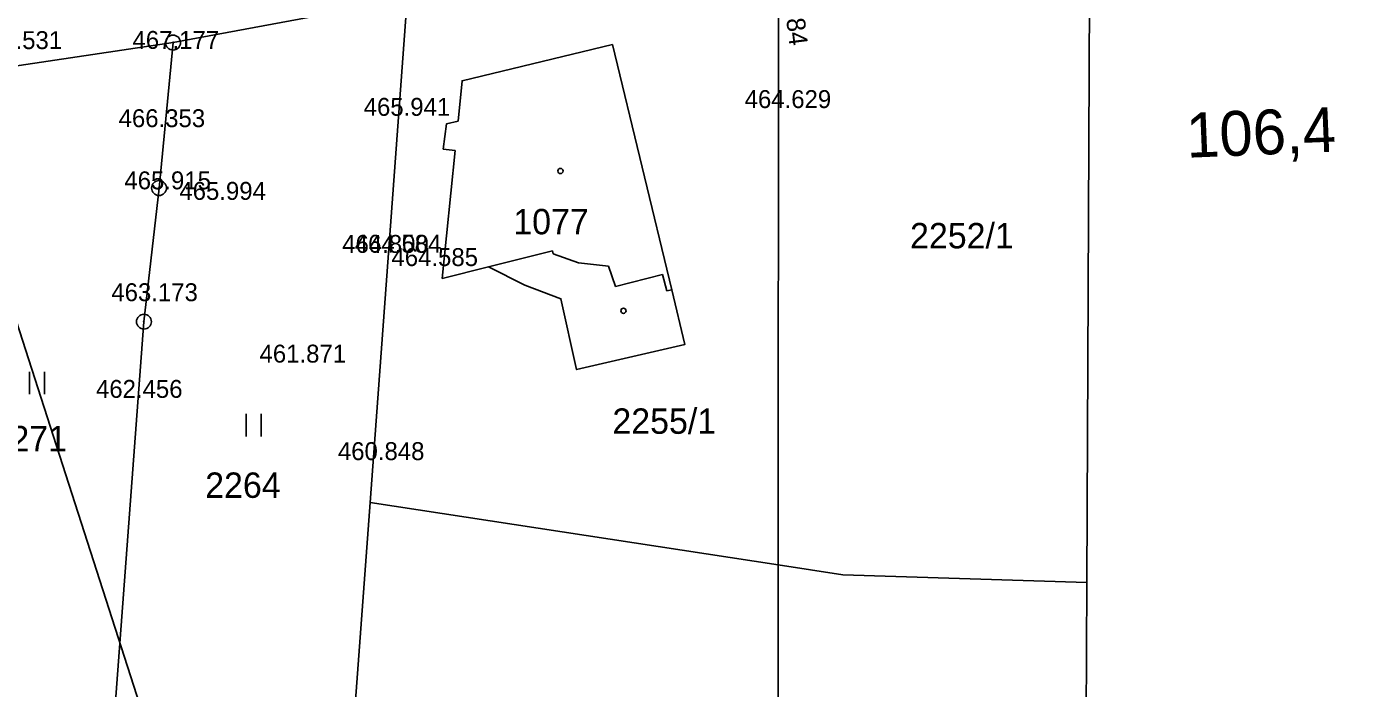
# Model space of a CAD drawing. Extents: x -758836 to -757729, y -1175316 to -1174366.
# Drawn here: x -758289.2 to -758200.5, y -1174833.7 to -1174789.4 of the extents above; entities that cross this region are included whole.
import ezdxf

# ---------------------------------------------------------------- set-up
doc = ezdxf.new("R2010")
doc.units = 0
for name, color, linetype in [('_NOR-návrh tenká', 7, 'Continuous'), ('_NOR-osa', 7, 'Continuous'), ('_NOR-pomocná', 7, 'Continuous'), ('_NOR-popis', 7, 'Continuous'), ('Hranice parcel', 7, 'Continuous'), ('Parcelní čísla', 7, 'Continuous'), ('Vnitřní kresba', 7, 'Continuous'), ('Vrstva 61', 7, 'Continuous'), ('Značky bodu BP', 7, 'Continuous'), ('Značky budov', 7, 'Continuous'), ('Značky kultur', 7, 'Continuous')]:
    doc.layers.add(name, color=color, linetype=linetype)

msp = doc.modelspace()

# ---------------------------------------------------------------- linework, layer by layer
at = {"layer": '_NOR-návrh tenká'}
for radius, start, end in [(295.6, 97.09776, 129.28488), (294.75, 97.0979, 129.28474), (293.75, 97.09807, 120.96729), (292.25, 97.09832, 120.96729), (291.3, 97.09848, 129.28417), (290.55, 97.09861, 129.28404)]:
    msp.add_arc((-758205.34, -1175057.864), radius, start, end, dxfattribs=at)
at = {"layer": '_NOR-osa'}
msp.add_arc((-758205.34, -1175057.864), 293, 97.09819, 129.28445, dxfattribs=at)
at = {"layer": '_NOR-pomocná'}
for points in [[(-758317.652, -1174723.031), (-758217.708, -1174690.839), (-758172.179, -1174832.187), (-758272.123, -1174864.38)], [(-758417.595, -1174755.224), (-758317.652, -1174723.031), (-758272.123, -1174864.38), (-758372.066, -1174896.572)]]:
    msp.add_lwpolyline(points, close=True, dxfattribs=at)
at = {"layer": 'Hranice parcel'}
for p, q in [((-758218.18, -1174826.63), (-758217.96, -1174778.94)), ((-758238.83, -1174781.6), (-758238.86, -1174825.45)), ((-758263.72, -1174787.54), (-758279.42, -1174790.47)), ((-758263.72, -1174787.54), (-758266.21, -1174821.26)), ((-758279.42, -1174790.47), (-758292.27, -1174792.38)), ((-758266.21, -1174821.26), (-758268.21, -1174848.52)), ((-758266.21, -1174821.26), (-758238.86, -1174825.45)), ((-758238.86, -1174825.45), (-758238.89, -1174870.98)), ((-758218.18, -1174826.63), (-758218.45, -1174888.34))]:
    msp.add_line(p, q, dxfattribs=at)
for points in [[(-758279.42, -1174790.47), (-758280.36, -1174800.21), (-758281.37, -1174809.16), (-758283.71, -1174840.27)], [(-758261.31, -1174797.61), (-758261.1, -1174795.92), (-758260.32, -1174795.73), (-758260.05, -1174793.03), (-758249.97, -1174790.6), (-758245.99, -1174807.02), (-758245.12, -1174810.68), (-758252.37, -1174812.37), (-758253.43, -1174807.62), (-758255.84, -1174806.71), (-758258.27, -1174805.48), (-758261.38, -1174806.26), (-758260.52, -1174797.7), (-758261.31, -1174797.61)], [(-758238.86, -1174825.45), (-758234.52, -1174826.12), (-758218.18, -1174826.63)]]:
    msp.add_lwpolyline(points, dxfattribs=at)
at = {"layer": 'Vnitřní kresba'}
for p, q in [((-758258.27, -1174805.48), (-758254, -1174804.41)), ((-758254, -1174804.41), (-758253.94, -1174804.62)), ((-758253.94, -1174804.62), (-758252.25, -1174805.23)), ((-758252.25, -1174805.23), (-758250.24, -1174805.45)), ((-758250.24, -1174805.45), (-758249.77, -1174806.81)), ((-758249.77, -1174806.81), (-758246.62, -1174805.99)), ((-758246.62, -1174805.99), (-758246.33, -1174807.1)), ((-758246.33, -1174807.1), (-758245.99, -1174807.02))]:
    msp.add_line(p, q, dxfattribs=at)
at = {"layer": 'Značky bodu BP'}
for centre, radius in [((-758279.42, -1174790.47), 0.5), ((-758279.42, -1174790.47), 0.0303), ((-758280.36, -1174800.21), 0.5), ((-758280.36, -1174800.21), 0.0303), ((-758281.37, -1174809.16), 0.5), ((-758281.37, -1174809.16), 0.0303)]:
    msp.add_circle(centre, radius, dxfattribs=at)
at = {"layer": 'Značky budov'}
for centre in [(-758253.457, -1174799.069), (-758249.237, -1174808.429)]:
    msp.add_circle(centre, 0.175, dxfattribs=at)
at = {"layer": 'Značky kultur'}
for p, q in [((-758289.031, -1174814.01), (-758289.031, -1174812.51)), ((-758288.03, -1174814.01), (-758288.03, -1174812.51)), ((-758274.511, -1174816.84), (-758274.511, -1174815.34)), ((-758273.51, -1174816.84), (-758273.51, -1174815.34))]:
    msp.add_line(p, q, dxfattribs=at)

# ---------------------------------------------------------------- texts
at = {"layer": '_NOR-popis'}
for s, height, rotation, p in [('KO km 106,366 984', 1.25, 277.09819, (-758239.938, -1174775.979)), ('106,4', 3, 2.3427, (-758211.462, -1174798.184))]:
    msp.add_text(s, height=height, rotation=rotation, dxfattribs=at).set_placement(p)
at = {"layer": 'Parcelní čísla'}
for s, p in [('1077', (-758256.617, -1174803.31)), ('2252/1', (-758230.025, -1174804.25)), ('2255/1', (-758249.975, -1174816.67)), ('2271', (-758291.587, -1174817.84)), ('2264', (-758277.267, -1174820.96))]:
    msp.add_text(s, height=1.7, dxfattribs=at).set_placement(p)
at = {"layer": 'Vrstva 61'}
for s, p in [('467.531', (-758292.655, -1174790.905)), ('467.177', (-758282.138, -1174790.891)), ('464.629', (-758241.111, -1174794.855)), ('465.941', (-758266.645, -1174795.374)), ('465.941', (-758266.645, -1174795.374)), ('466.353', (-758283.07, -1174796.133)), ('465.915', (-758282.683, -1174800.296)), ('465.915', (-758282.683, -1174800.296)), ('465.994', (-758278.998, -1174801.002)), ('464.800', (-758268.083, -1174804.555)), ('464.584', (-758267.241, -1174804.542)), ('464.584', (-758267.241, -1174804.542)), ('464.585', (-758264.782, -1174805.436)), ('463.173', (-758283.558, -1174807.788)), ('461.871', (-758273.625, -1174811.901)), ('462.456', (-758284.586, -1174814.261)), ('460.848', (-758268.373, -1174818.431)), ('460.848', (-758268.373, -1174818.431))]:
    msp.add_text(s, height=1.2, dxfattribs=at).set_placement(p)

doc.saveas('drawing.dxf')
